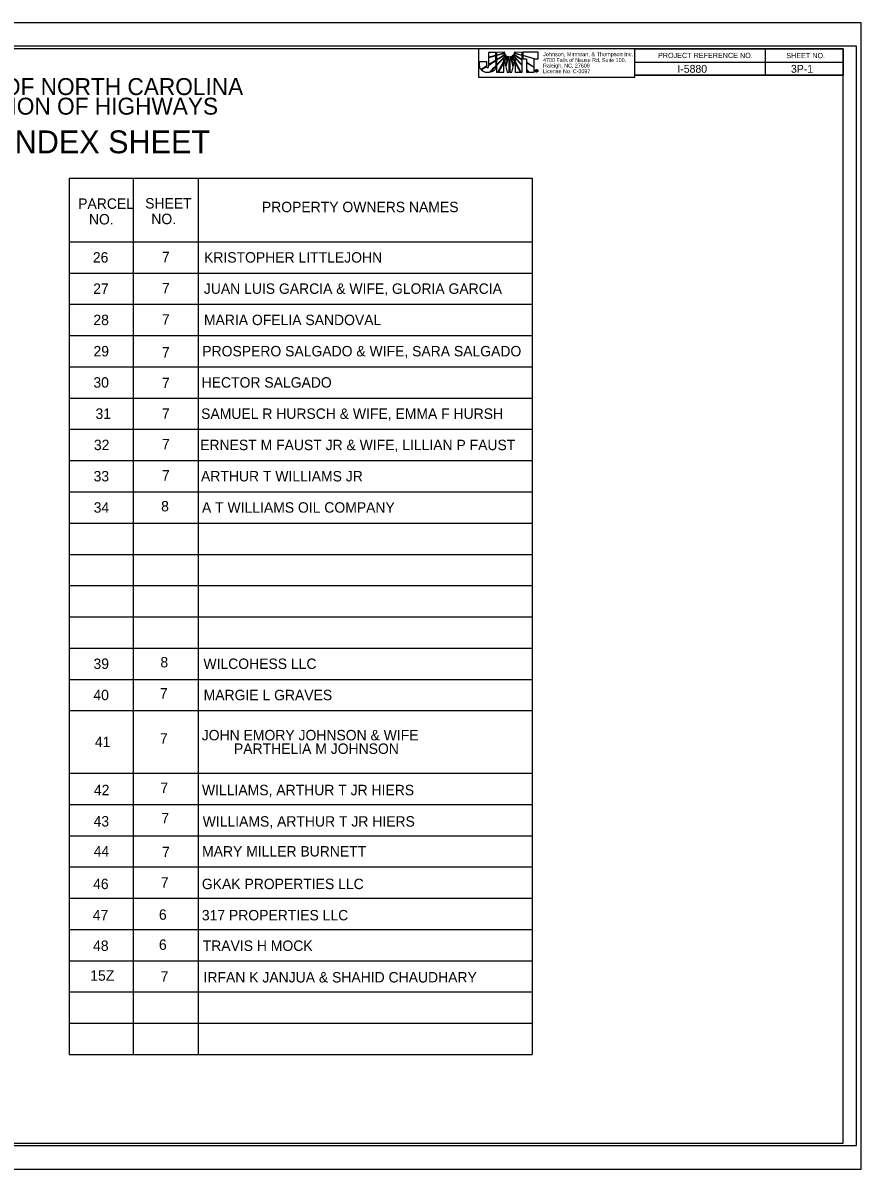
# Model space of a CAD drawing. Extents: x 1729874 to 1731665, y 539736 to 540836.
# Drawn here: x 1730861 to 1731665, y 539736 to 540836 of the extents above; entities that cross this region are included whole.
import ezdxf

# ---------------------------------------------------------------- set-up
doc = ezdxf.new("R2010")
doc.units = 0
for name, color, linetype in [('Prop Dimension Text', 7, 'Continuous'), ('Sheet Data Field CELL', 7, 'Continuous'), ('Sheet Plot Border Inside CELL', 7, 'Continuous'), ('Sheet Plot Border Outside CELL', 7, 'Continuous'), ('Sheet Summary CELL', 7, 'Continuous')]:
    doc.layers.add(name, color=color, linetype=linetype)

msp = doc.modelspace()

# ---------------------------------------------------------------- linework, layer by layer
at = {"layer": 'Prop Dimension Text'}
for p, q in [((1731314.5, 540808), (1731307.4, 540808)), ((1731307.4, 540808), (1731307.4, 540803.3)), ((1731307.4, 540803.3), (1731314.5, 540805.3)), ((1731314.5, 540804.8), (1731307.4, 540802.8)), ((1731314.5, 540805.3), (1731314.5, 540808)), ((1731314.5, 540800.7), (1731314.5, 540804.8)), ((1731323.1, 540808.1), (1731315.2, 540808)), ((1731315.2, 540808), (1731315.2, 540805.5)), ((1731315.2, 540805.5), (1731321.1, 540807.2)), ((1731321.1, 540806.6), (1731315.2, 540805)), ((1731315.2, 540805), (1731315.2, 540801.2)), ((1731315.2, 540801.2), (1731320.5, 540804.5)), ((1731321.3, 540804.5), (1731315.2, 540800.6)), ((1731320.5, 540804.5), (1731323.4, 540806.9)), ((1731321.1, 540807.2), (1731323.1, 540808.1)), ((1731323.4, 540806.9), (1731321.1, 540806.6)), ((1731323.9, 540805.8), (1731321.3, 540804.5)), ((1731322.6, 540803.9), (1731323.9, 540805.8)), ((1731324.8, 540805), (1731322.9, 540803.5)), ((1731323.9, 540802.7), (1731324.8, 540805)), ((1731325.8, 540804.3), (1731324.4, 540802.6)), ((1731325.6, 540802.2), (1731325.8, 540804.3)), ((1731326.9, 540804), (1731326, 540801.8)), ((1731327.2, 540798.5), (1731326.9, 540804)), ((1731328.1, 540804), (1731327.7, 540798.5)), ((1731329, 540801.8), (1731328.1, 540804)), ((1731329.2, 540804.3), (1731329.4, 540802.1)), ((1731330.6, 540802.6), (1731329.2, 540804.3)), ((1731330.2, 540805), (1731331.1, 540802.7)), ((1731332.1, 540803.5), (1731330.2, 540805)), ((1731331, 540805.8), (1731332.4, 540803.9)), ((1731333.7, 540804.5), (1731331, 540805.8)), ((1731331.6, 540806.9), (1731334.6, 540804.5)), ((1731333.8, 540806.6), (1731331.6, 540806.9)), ((1731339.8, 540808), (1731332, 540808.1)), ((1731332, 540808.1), (1731334, 540807.1)), ((1731339.8, 540800.6), (1731333.7, 540804.5)), ((1731339.8, 540805), (1731333.8, 540806.6)), ((1731334, 540807.1), (1731339.8, 540805.5)), ((1731334.6, 540804.5), (1731339.8, 540801.3)), ((1731339.8, 540805.5), (1731339.8, 540808)), ((1731339.8, 540801.3), (1731339.8, 540805)), ((1731355.1, 540808.1), (1731340.3, 540808.1)), ((1731340.3, 540808.1), (1731340.3, 540805.4)), ((1731340.3, 540805.4), (1731340.3, 540805.3)), ((1731340.3, 540805.3), (1731352, 540802)), ((1731340.3, 540804.9), (1731340.3, 540804.8)), ((1731351.2, 540801.8), (1731340.3, 540804.9)), ((1731340.3, 540804.8), (1731340.4, 540802)), ((1731355.1, 540802), (1731355.1, 540808.1)), ((1731307.4, 540802.8), (1731307.4, 540796.3)), ((1731307.4, 540796.3), (1731314.5, 540800.7)), ((1731315.2, 540796.2), (1731322.6, 540803.9)), ((1731322.9, 540803.5), (1731315.2, 540795.5)), ((1731315.2, 540800.6), (1731315.2, 540796.2)), ((1731315.2, 540795.5), (1731315.2, 540789.1)), ((1731316.4, 540789.1), (1731322.1, 540799.5)), ((1731322.1, 540798.5), (1731316.9, 540789.1)), ((1731322.1, 540799.5), (1731322.1, 540801.3)), ((1731322.1, 540801.3), (1731322.4, 540800)), ((1731322.1, 540789.1), (1731322.1, 540798.5)), ((1731322.4, 540800), (1731323.9, 540802.7)), ((1731324.4, 540802.6), (1731322.6, 540799.4)), ((1731322.6, 540799.4), (1731323.8, 540795.2)), ((1731323.8, 540795.2), (1731325.6, 540802.2)), ((1731326, 540801.8), (1731324, 540794.2)), ((1731324, 540794.2), (1731325.3, 540789.1)), ((1731327.2, 540789.1), (1731327.2, 540798.5)), ((1731327.7, 540798.5), (1731327.7, 540789.1)), ((1731331, 540794.1), (1731329, 540801.8)), ((1731329.4, 540802.1), (1731331.3, 540795)), ((1731329.7, 540789.1), (1731331, 540794.1)), ((1731332.4, 540799.3), (1731330.6, 540802.6)), ((1731331.1, 540802.7), (1731332.6, 540799.9)), ((1731331.3, 540795), (1731332.4, 540799.3)), ((1731339.8, 540795.4), (1731332.1, 540803.5)), ((1731332.4, 540803.9), (1731339.8, 540796.1)), ((1731332.6, 540799.9), (1731332.9, 540801.3)), ((1731332.9, 540801.3), (1731332.9, 540799.3)), ((1731332.9, 540799.3), (1731338.5, 540789.1)), ((1731338, 540789.1), (1731332.9, 540798.3)), ((1731332.9, 540798.3), (1731332.9, 540789.1)), ((1731339.8, 540796.1), (1731339.8, 540800.6)), ((1731339.8, 540789.1), (1731339.8, 540795.4)), ((1731340.4, 540802), (1731344, 540802)), ((1731344, 540802), (1731344, 540798.6)), ((1731344, 540798.6), (1731351.2, 540794)), ((1731344, 540798), (1731344, 540791.8)), ((1731351.2, 540793.5), (1731344, 540798)), ((1731351.2, 540794), (1731351.2, 540801.8)), ((1731351.2, 540789.1), (1731351.2, 540793.5)), ((1731352, 540802), (1731355.1, 540802)), ((1731315.2, 540789.1), (1731316.4, 540789.1)), ((1731316.9, 540789.1), (1731322.1, 540789.1)), ((1731325.3, 540789.1), (1731327.2, 540789.1)), ((1731327.7, 540789.1), (1731329.7, 540789.1)), ((1731332.9, 540789.1), (1731338, 540789.1)), ((1731338.5, 540789.1), (1731339.8, 540789.1)), ((1731344, 540791.8), (1731346.5, 540789.1)), ((1731345.8, 540789.1), (1731344, 540791.1)), ((1731344, 540791.1), (1731344, 540789.1)), ((1731344, 540789.1), (1731345.8, 540789.1)), ((1731346.5, 540789.1), (1731351.2, 540789.1)), ((1731353.1, 540789.8), (1731353.1, 540790.9)), ((1731353.1, 540790.9), (1731353.5, 540790.9)), ((1731353.3, 540789.8), (1731353.1, 540789.8)), ((1731353.5, 540790.7), (1731353.3, 540790.7)), ((1731353.3, 540790.7), (1731353.3, 540790.4)), ((1731353.3, 540790.4), (1731353.5, 540790.4)), ((1731353.5, 540790.2), (1731353.3, 540790.2)), ((1731353.3, 540790.2), (1731353.3, 540789.8)), ((1731353.5, 540791.5), (1731353.5, 540791.3)), ((1731353.5, 540791.3), (1731353.5, 540791.5)), ((1731353.5, 540790.9), (1731353.5, 540790.7)), ((1731353.5, 540790.7), (1731353.5, 540790.9)), ((1731353.5, 540790.9), (1731353.6, 540790.9)), ((1731353.6, 540790.7), (1731353.5, 540790.7)), ((1731353.5, 540790.4), (1731353.5, 540790.2)), ((1731353.5, 540790.2), (1731353.5, 540790.4)), ((1731353.5, 540790.4), (1731353.5, 540790.4)), ((1731353.5, 540790.2), (1731353.5, 540790.2)), ((1731353.5, 540789.4), (1731353.5, 540789.1)), ((1731353.5, 540789.1), (1731353.5, 540789.4)), ((1731353.5, 540789.4), (1731353.5, 540789.4)), ((1731353.5, 540789.1), (1731353.5, 540789.1))]:
    msp.add_line(p, q, dxfattribs=at)
msp.add_lwpolyline([(1731297.9, 540784.3), (1731447.9, 540784.3), (1731447.9, 540811.3), (1731297.9, 540811.3)], close=True, dxfattribs=at)
for points in [[(1731307.4, 540803.3), (1731314.5, 540805.3), (1731314.5, 540808), (1731307.4, 540808), (1731307.4, 540803.3)], [(1731307.4, 540796.3), (1731314.5, 540800.7), (1731314.5, 540804.8), (1731307.4, 540802.8), (1731307.4, 540796.3)], [(1731321.1, 540807.2), (1731323.1, 540808.1), (1731315.2, 540808), (1731315.2, 540805.5), (1731321.1, 540807.2)], [(1731315.2, 540805), (1731315.2, 540801.2), (1731320.5, 540804.5), (1731323.4, 540806.9), (1731321.1, 540806.6), (1731315.2, 540805)], [(1731315.2, 540800.6), (1731315.2, 540796.2), (1731322.6, 540803.9), (1731323.9, 540805.8), (1731321.3, 540804.5), (1731315.2, 540800.6)], [(1731324.8, 540805), (1731322.9, 540803.5), (1731315.2, 540795.5), (1731315.2, 540789.1), (1731316.4, 540789.1), (1731322.1, 540799.5), (1731322.1, 540801.3), (1731322.4, 540800), (1731323.9, 540802.7), (1731324.8, 540805)], [(1731325.8, 540804.3), (1731324.4, 540802.6), (1731322.6, 540799.4), (1731323.8, 540795.2), (1731325.6, 540802.2), (1731325.8, 540804.3)], [(1731326, 540801.8), (1731324, 540794.2), (1731325.3, 540789.1), (1731327.2, 540789.1), (1731327.2, 540798.5), (1731326.9, 540804), (1731326, 540801.8)], [(1731328.1, 540804), (1731327.7, 540798.5), (1731327.7, 540789.1), (1731329.7, 540789.1), (1731331, 540794.1), (1731329, 540801.8), (1731328.1, 540804)], [(1731329.2, 540804.3), (1731329.4, 540802.1), (1731331.3, 540795), (1731332.4, 540799.3), (1731330.6, 540802.6), (1731329.2, 540804.3)], [(1731330.2, 540805), (1731331.1, 540802.7), (1731332.6, 540799.9), (1731332.9, 540801.3), (1731332.9, 540799.3), (1731338.5, 540789.1), (1731339.8, 540789.1), (1731339.8, 540795.4), (1731332.1, 540803.5), (1731330.2, 540805)], [(1731331, 540805.8), (1731332.4, 540803.9), (1731339.8, 540796.1), (1731339.8, 540800.6), (1731333.7, 540804.5), (1731331, 540805.8)], [(1731331.6, 540806.9), (1731334.6, 540804.5), (1731339.8, 540801.3), (1731339.8, 540805), (1731333.8, 540806.6), (1731331.6, 540806.9)], [(1731334, 540807.1), (1731339.8, 540805.5), (1731339.8, 540808), (1731332, 540808.1), (1731334, 540807.1)], [(1731355.1, 540808.1), (1731340.3, 540808.1), (1731340.3, 540805.4), (1731340.3, 540805.3), (1731352, 540802), (1731355.1, 540802), (1731355.1, 540808.1)], [(1731340.3, 540804.9), (1731340.3, 540804.8), (1731340.4, 540802), (1731344, 540802), (1731344, 540798.6), (1731351.2, 540794), (1731351.2, 540801.8), (1731340.3, 540804.9)], [(1731316.9, 540789.1), (1731322.1, 540789.1), (1731322.1, 540798.5), (1731316.9, 540789.1)], [(1731332.9, 540789.1), (1731338, 540789.1), (1731332.9, 540798.3), (1731332.9, 540789.1)], [(1731344, 540798), (1731344, 540791.8), (1731346.5, 540789.1), (1731351.2, 540789.1), (1731351.2, 540793.5), (1731344, 540798), (1731344, 540798)], [(1731344, 540789.1), (1731344, 540789.1), (1731345.8, 540789.1), (1731344, 540791.1), (1731344, 540789.1)], [(1731354, 540790), (1731354, 540790), (1731354, 540789.9), (1731354, 540789.9), (1731354, 540789.8), (1731353.8, 540789.8)]]:
    msp.add_lwpolyline(points, dxfattribs=at)
for points, degree in [([(1731305.4, 540799.3), (1731305.4, 540799.3), (1731298.9, 540799.3), (1731298.9, 540799.3), (1731298.9, 540799.3), (1731298.9, 540795.2), (1731298.9, 540795.2), (1731298.9, 540795.2), (1731298.9, 540794.8), (1731298.9, 540794.8), (1731298.9, 540793.5), (1731299.4, 540792.5), (1731300.1, 540791.7), (1731300.1, 540791.7), (1731305.4, 540794.9), (1731305.4, 540795), (1731305.4, 540795), (1731305.4, 540799.3), (1731305.4, 540799.3)], 3), ([(1731306.4, 540793.4), (1731306, 540793.4), (1731305.7, 540793.7), (1731305.5, 540794.4), (1731305.5, 540794.4), (1731300.5, 540791.3), (1731300.5, 540791.3), (1731302, 540789.7), (1731304.5, 540788.7), (1731306.6, 540788.7), (1731307.2, 540788.7), (1731307.6, 540788.8), (1731308.1, 540788.9), (1731308.1, 540788.9), (1731314.5, 540795.4), (1731314.5, 540795.4), (1731314.5, 540795.4), (1731314.5, 540800.1), (1731314.5, 540800.1), (1731314.5, 540800.1), (1731307.4, 540795.7), (1731307.4, 540795.7), (1731307.4, 540793.9), (1731307, 540793.4), (1731306.4, 540793.4)], 3), ([(1731306.4, 540793.4), (1731306, 540793.4), (1731305.7, 540793.7), (1731305.5, 540794.4), (1731305.5, 540794.4), (1731300.5, 540791.3), (1731300.5, 540791.3), (1731302, 540789.7), (1731304.5, 540788.7), (1731306.6, 540788.7), (1731307.2, 540788.7), (1731307.6, 540788.8), (1731308.1, 540788.9), (1731308.1, 540788.9), (1731314.5, 540795.4), (1731314.5, 540795.4), (1731314.5, 540795.4), (1731314.5, 540800.1), (1731314.5, 540800.1), (1731314.5, 540800.1), (1731307.4, 540795.7), (1731307.4, 540795.7), (1731307.4, 540793.9), (1731307, 540793.4), (1731306.4, 540793.4)], 3), ([(1731314.5, 540794.7), (1731314.5, 540794.7), (1731309, 540789), (1731309, 540789), (1731311.7, 540789.7), (1731314.3, 540791.5), (1731314.5, 540794.7)], 3), ([(1731353.5, 540789.1), (1731353.2, 540789.1), (1731352.9, 540789.3), (1731352.7, 540789.5), (1731352.5, 540789.7), (1731352.3, 540790), (1731352.3, 540790.3), (1731352.3, 540790.7), (1731352.4, 540790.9), (1731352.7, 540791.2), (1731352.9, 540791.4), (1731353.2, 540791.5), (1731353.5, 540791.5)], 3), ([(1731353.5, 540791.3), (1731353.3, 540791.3), (1731353, 540791.2), (1731352.8, 540791), (1731352.7, 540790.8), (1731352.6, 540790.6), (1731352.6, 540790.3), (1731352.6, 540790.1), (1731352.7, 540789.8), (1731352.9, 540789.6), (1731353, 540789.5), (1731353.3, 540789.4), (1731353.5, 540789.4)], 3), ([(1731353.5, 540791.5), (1731353.9, 540791.5), (1731354.1, 540791.4), (1731354.4, 540791.2), (1731354.6, 540790.9), (1731354.7, 540790.7), (1731354.7, 540790.3)], 3), ([(1731353.5, 540789.4), (1731353.8, 540789.4), (1731354, 540789.5), (1731354.2, 540789.6), (1731354.4, 540789.8), (1731354.5, 540790.1), (1731354.5, 540790.3), (1731354.5, 540790.6), (1731354.4, 540790.8), (1731354.2, 540791), (1731354, 540791.2), (1731353.8, 540791.3), (1731353.5, 540791.3)], 3), ([(1731353.5, 540790.4), (1731353.7, 540790.4), (1731353.8, 540790.5), (1731353.8, 540790.5), (1731353.8, 540790.6), (1731353.7, 540790.7), (1731353.6, 540790.7)], 3), ([(1731354.7, 540790.3), (1731354.7, 540790), (1731354.6, 540789.7), (1731354.4, 540789.5), (1731354.1, 540789.3), (1731353.9, 540789.1), (1731353.5, 540789.1)], 3), ([(1731353.7, 540790.2), (1731353.7, 540790.2), (1731353.6, 540790.2), (1731353.5, 540790.2)], 2), ([(1731353.6, 540790.9), (1731353.9, 540790.9), (1731354, 540790.8), (1731354, 540790.5), (1731354, 540790.4), (1731354, 540790.4), (1731353.9, 540790.3)], 3), ([(1731353.8, 540789.8), (1731353.8, 540789.8), (1731353.8, 540789.9), (1731353.8, 540790), (1731353.8, 540790.1), (1731353.7, 540790.1), (1731353.7, 540790.2)], 3), ([(1731353.9, 540790.3), (1731353.9, 540790.3), (1731354, 540790.2), (1731354, 540790)], 2)]:
    msp.add_open_spline(points, degree=degree, dxfattribs=at)
at = {"layer": 'Sheet Plot Border Inside CELL'}
msp.add_lwpolyline([(1731660.4, 540813.9), (1729993.9, 540813.9), (1729993.9, 539758.8), (1731660.4, 539758.8)], close=True, dxfattribs=at)
at = {"layer": 'Sheet Plot Border Outside CELL'}
msp.add_lwpolyline([(1731664.9, 540836.3), (1729980.9, 540836.3), (1729980.9, 539736.3), (1731664.9, 539736.3)], close=True, dxfattribs=at)
at = {"layer": 'Sheet Summary CELL'}
for p, q in [((1731572.9, 540811.3), (1731572.9, 540786.3)), ((1731447.9, 540798.8), (1731647.9, 540798.8)), ((1731447.9, 540786.3), (1731647.9, 540786.3)), ((1730904.8, 540687.2), (1731291.5, 540687.2)), ((1730904.8, 540687.2), (1731349.4, 540687.2)), ((1730904.8, 540687.2), (1730904.8, 539846.3)), ((1730966.4, 540687.2), (1730966.4, 539846.3)), ((1731028.6, 540687.2), (1731028.6, 539846.3)), ((1731349.4, 540687.2), (1731349.4, 539846.3)), ((1730904.8, 540626.3), (1731349.4, 540626.3)), ((1730904.8, 540596.3), (1731349.4, 540596.3)), ((1730904.8, 540566.3), (1731349.4, 540566.3)), ((1730904.8, 540536.3), (1731349.4, 540536.3)), ((1730904.8, 540506.3), (1731349.4, 540506.3)), ((1730904.8, 540476.3), (1731349.4, 540476.3)), ((1730904.8, 540446.3), (1731349.4, 540446.3)), ((1730904.8, 540416.3), (1731349.4, 540416.3)), ((1730904.8, 540386.3), (1731349.4, 540386.3)), ((1730904.8, 540356.3), (1731349.4, 540356.3)), ((1730904.8, 540326.3), (1731349.4, 540326.3)), ((1730904.8, 540296.3), (1731349.4, 540296.3)), ((1730904.8, 540266.3), (1731349.4, 540266.3)), ((1730904.8, 540236.3), (1731349.4, 540236.3)), ((1730904.8, 540206.3), (1731349.4, 540206.3)), ((1730904.8, 540176.3), (1731349.4, 540176.3)), ((1730904.8, 540116.3), (1731349.4, 540116.3)), ((1730904.8, 540086.3), (1731349.4, 540086.3)), ((1730904.8, 540056.3), (1731349.4, 540056.3)), ((1730904.8, 540026.3), (1731349.4, 540026.3)), ((1730904.8, 539996.3), (1731349.4, 539996.3)), ((1730904.8, 539966.3), (1731349.4, 539966.3)), ((1730904.8, 539936.3), (1731349.4, 539936.3)), ((1730904.8, 539906.3), (1731349.4, 539906.3)), ((1730904.8, 539876.3), (1731349.4, 539876.3)), ((1730904.8, 539846.3), (1731349.4, 539846.3))]:
    msp.add_line(p, q, dxfattribs=at)
for points in [[(1731647.9, 540811.3), (1730147.9, 540811.3), (1730147.9, 539761.3), (1731647.9, 539761.3)], [(1731447.9, 540811.3), (1731647.9, 540811.3), (1731647.9, 540786.3), (1731447.9, 540786.3)]]:
    msp.add_lwpolyline(points, close=True, dxfattribs=at)

# ---------------------------------------------------------------- texts
at = {"layer": 'Prop Dimension Text'}
for s, height, p in [('Johnson, Mirmiran, & Thompson Inc.', 3.831, (1731359.7, 540804.4)), ('4700 Falls of Neuse Rd, Suite 100, ', 3.722, (1731359.7, 540798.8)), ('Raleigh, NC, 27609', 3.722, (1731359.7, 540793.5)), ('License No: C-3097', 3.722, (1731359.7, 540788.1))]:
    msp.add_text(s, height=height, rotation=360, dxfattribs=at).set_placement(p)
at = {"layer": 'Sheet Data Field CELL'}
for s, p in [('I-5880', (1731488.7, 540788.5)), ('3P-1', (1731597.7, 540788.5))]:
    msp.add_text(s, height=7.5, rotation=0, dxfattribs=at).set_placement(p)
at = {"layer": 'Sheet Summary CELL'}
for s, height, p in [('PROJECT REFERENCE NO.', 5, (1731470.1, 540802.6)), ('SHEET NO.', 5, (1731593.2, 540802.5)), ('STATE OF NORTH CAROLINA', 16.25, (1730765.3, 540767.1)), ('DIVISION OF HIGHWAYS', 16.25, (1730791.9, 540748.3)), ('PARCEL INDEX SHEET', 21.95, (1730718.9, 540711.2)), ('PARCEL', 10, (1730913.6, 540657.9)), ('SHEET ', 10, (1730977.9, 540658.2)), ('PROPERTY OWNERS NAMES ', 10, (1731089.9, 540654.7)), ('NO. ', 10, (1730923.9, 540642.9)), ('NO.', 10, (1730983.8, 540643.2)), ('26', 10, (1730927.7, 540606.3)), ('7', 10, (1730994, 540606.7)), ('KRISTOPHER LITTLEJOHN', 10, (1731034.4, 540606.3)), ('27', 10, (1730928, 540576.3)), ('7', 10, (1730994, 540576.7)), ('JUAN LUIS GARCIA & WIFE, GLORIA GARCIA', 10, (1731034.2, 540576.3)), ('28', 10, (1730928.2, 540546.3)), ('7', 10, (1730994, 540546.8)), ('MARIA OFELIA SANDOVAL', 10, (1731034.3, 540546.3)), ('29', 10, (1730928.3, 540516.3)), ('7', 10, (1730994, 540515.2)), ('PROSPERO SALGADO & WIFE, SARA SALGADO', 10, (1731032.7, 540516.3)), ('30', 10, (1730928.2, 540486.3)), ('HECTOR SALGADO', 10, (1731032.1, 540486.3)), ('7', 10, (1730994, 540485.8)), ('31', 10, (1730930.2, 540456.3)), ('7', 10, (1730994, 540456.4)), ('SAMUEL R HURSCH & WIFE, EMMA F HURSH', 10, (1731031.6, 540456.3)), ('32', 10, (1730928.7, 540426.3)), ('7', 10, (1730994, 540427)), ('ERNEST M FAUST JR & WIFE, LILLIAN P FAUST', 10, (1731030.7, 540426.3)), ('33', 10, (1730928.4, 540396.3)), ('7', 10, (1730994, 540397.1)), ('ARTHUR T WILLIAMS JR', 10, (1731031.5, 540396.3)), ('34', 10, (1730928.5, 540366.3)), ('8', 10, (1730993.2, 540367.5)), ('A T WILLIAMS OIL COMPANY', 10, (1731032.4, 540366.3)), ('39', 10, (1730928.3, 540216.3)), ('8', 10, (1730992.5, 540217.8)), ('WILCOHESS LLC', 10, (1731033.8, 540216.3)), ('40', 10, (1730928.2, 540186.3)), ('7', 10, (1730992, 540187.9)), ('MARGIE L GRAVES', 10, (1731034, 540186.3)), ('JOHN EMORY JOHNSON & WIFE', 10, (1731032.2, 540147.8)), ('41', 10, (1730929.6, 540141.3)), ('7', 10, (1730992.1, 540144.6)), ('PARTHELIA M JOHNSON', 10, (1731063.1, 540134.8)), ('42', 10, (1730928.7, 540095.1)), ('7', 10, (1730992.5, 540097.3)), ('WILLIAMS, ARTHUR T JR HIERS', 10, (1731032.4, 540095.1)), ('7', 10, (1730993.4, 540068.1)), ('43', 10, (1730928.4, 540065.1)), ('WILLIAMS, ARTHUR T JR HIERS', 10, (1731033.1, 540065)), ('44', 10, (1730928.5, 540036.3)), ('7', 10, (1730994.1, 540035.7)), ('MARY MILLER BURNETT', 10, (1731032.5, 540036.3)), ('46', 10, (1730927.9, 540005)), ('7', 10, (1730992.9, 540006.3)), ('GKAK PROPERTIES LLC', 10, (1731032.3, 540005)), ('47', 10, (1730927.6, 539975)), ('6', 10, (1730991.1, 539975.6)), ('317 PROPERTIES LLC', 10, (1731032.3, 539975)), ('48', 10, (1730927.9, 539945.7)), ('6', 10, (1730991.1, 539946.7)), ('TRAVIS H MOCK', 10, (1731033.1, 539945.7)), ('15Z', 10, (1730925.2, 539917.1)), ('7', 10, (1730992.7, 539916.1)), ('IRFAN K JANJUA & SHAHID CHAUDHARY', 10, (1731033.9, 539915.4))]:
    msp.add_text(s, height=height, dxfattribs=at).set_placement(p)

doc.saveas('drawing.dxf')
